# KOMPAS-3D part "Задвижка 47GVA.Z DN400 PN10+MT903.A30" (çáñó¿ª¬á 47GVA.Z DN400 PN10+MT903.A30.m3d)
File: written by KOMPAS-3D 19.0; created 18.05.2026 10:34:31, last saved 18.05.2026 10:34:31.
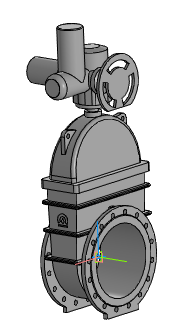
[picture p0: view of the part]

Document properties: Автор: Энергия; Полное имя файла: ..\Задвижка 47GVA.Z DN350_DN1200+MT903.A\Задвижка 47GVA.Z DN400 PN10+MT903.A30.a3d

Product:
- Part/product: Задвижка 47GVA.Z DN400 PN10+MT903.A30
    Масса: 752.289
  - Body: Электропривод МТ903.А30 без блока управления
      Масса: 163.268
  - Body: Задвижка 47GV.Z DN400 PN10 без исполнительного механизма
      Масса: 589.021

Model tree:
1. Операция без истории:1
2. Операция без истории:2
